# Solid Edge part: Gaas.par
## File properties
Author: Türk
Template: Iso Part.par
Last saved by: Türk
Revision: 9
Application: Solid Edge
Accuracy: 0,990
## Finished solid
Body 1: solid body, 42 faces, 101 edges, 60 vertices.
  Faces by surface: plane 23, spline 6, cylinder 5, swept 5, cone 3
  Edges by curve: line 44, curve on surface 26, circle 15, intersection 7, spline 5, ellipse 4
Bounding box of the edges (mm; curved faces can reach further): 56.952 x 70.000 x 202.196, from (-22.5, -30, -22.5) to (34.4517, 40, 179.6962).
Cylindrical faces by radius (mm): R10 x3, R21.8119 x1, R22.5 x1
Conical faces (half-angle, radius in mm at the cone's reference point): 45 deg R9 x1, 45 deg R21.8119 x1, 45 deg R47.5 x1
Planar faces by outward normal: +x 1, +y 3, +z 1, -x 1, -y 4, -z 3, oblique 10
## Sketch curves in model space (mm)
line (5, 0, 160) -> (5, 0, 125)
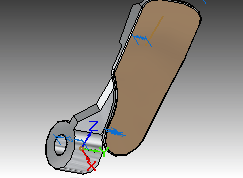
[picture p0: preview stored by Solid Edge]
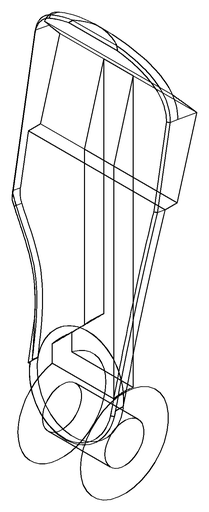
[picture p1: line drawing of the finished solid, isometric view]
